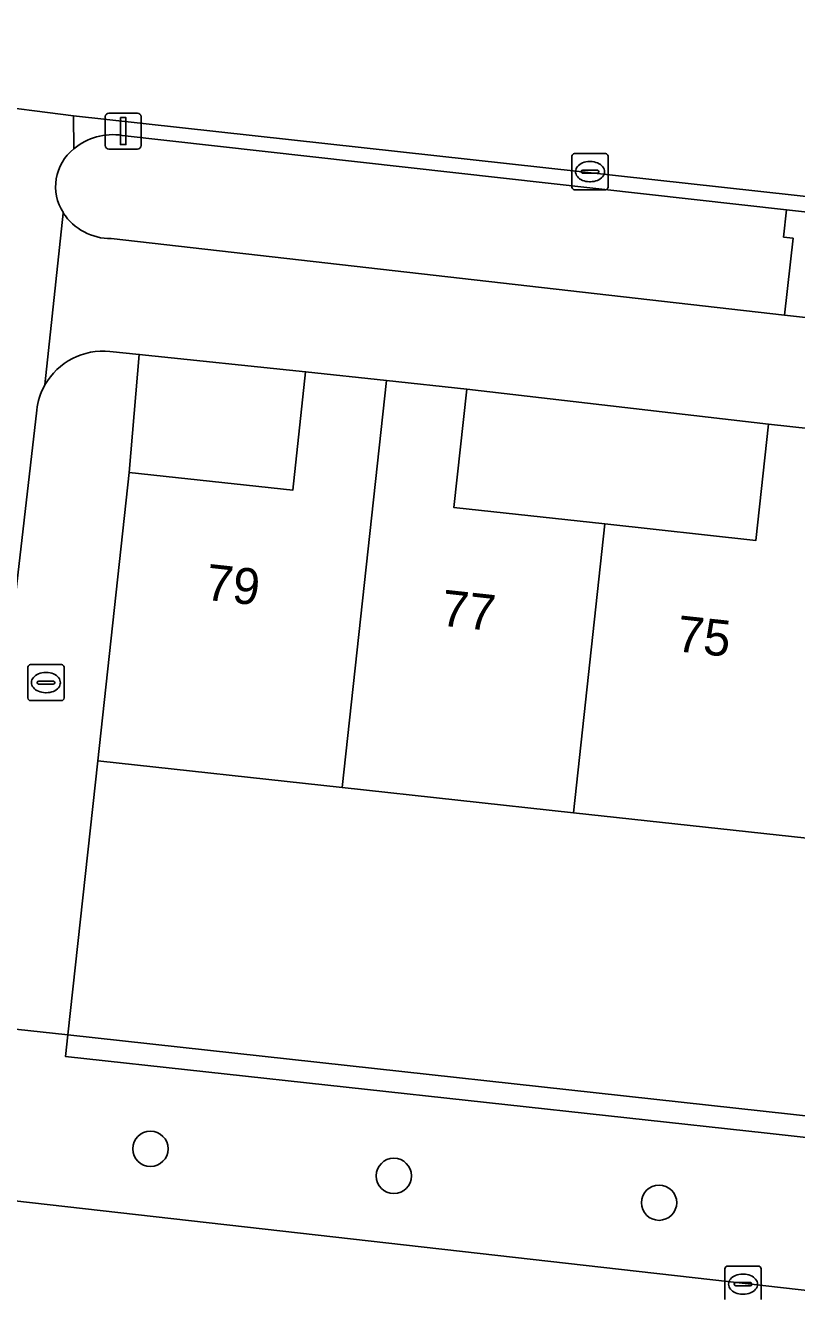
# Model space of a CAD drawing. Extents: x 161928 to 163071, y 386474 to 387428.
# Drawn here: x 162119.35 to 162140.71, y 387057.88 to 387093.2 of the extents above; entities that cross this region are included whole.
import ezdxf

# ---------------------------------------------------------------- set-up
doc = ezdxf.new("R2010")
doc.units = 0
for name, color, linetype in [('IMGEO_Boom', 7, 'Continuous'), ('IMGEO_Erf', 7, 'Continuous'), ('IMGEO_Groenvoorziening', 7, 'Continuous'), ('IMGEO_Haag', 7, 'Continuous'), ('IMGEO_Kolk', 7, 'Continuous'), ('IMGEO_Lichtmast', 7, 'Continuous'), ('IMGEO_Pand', 7, 'Continuous'), ('IMGEO_Pand_nummerreeks', 7, 'Continuous'), ('IMGEO_Rijbaan_lokaal_open', 7, 'Continuous'), ('IMGEO_Rioolput', 7, 'Continuous'), ('IMGEO_Voetpad_open', 7, 'Continuous')]:
    doc.layers.add(name, color=color, linetype=linetype)

msp = doc.modelspace()

# ---------------------------------------------------------------- linework, layer by layer
at = {"layer": 'IMGEO_Boom'}
for centre in [(162122.809, 387062.054), (162129.553, 387061.304), (162136.902, 387060.56)]:
    msp.add_circle(centre, 0.489, dxfattribs=at)
at = {"layer": 'IMGEO_Erf'}
for points in [[(162122.221, 387080.808), (162126.751, 387080.315), (162127.109, 387083.598), (162122.499, 387084.078)], [(162131.573, 387083.112), (162131.216, 387079.834), (162135.4, 387079.379), (162139.586, 387078.923), (162139.937, 387082.143)], [(162166.885, 387067.852), (162160.394, 387068.559), (162153.9, 387069.266), (162147.468, 387069.966), (162140.997, 387070.67), (162134.529, 387071.374), (162128.119, 387072.072), (162121.35, 387072.809), (162120.517, 387065.213), (162142.895, 387062.759), (162143.041, 387063.946), (162146.748, 387063.493), (162146.609, 387062.352), (162146.503, 387061.486), (162172.556, 387058.628), (162172.666, 387059.494), (162173.539, 387067.128)]]:
    msp.add_lwpolyline(points, close=True, dxfattribs=at)
at = {"layer": 'IMGEO_Groenvoorziening'}
for points in [[(162140.437, 387088.086), (162122.028, 387090.153)], [(162121.722, 387087.293), (162140.374, 387085.172), (162140.616, 387087.302), (162140.353, 387087.332), (162140.437, 387088.086)], [(162122.221, 387080.808), (162122.499, 387084.078), (162121.687, 387084.163)], [(162119.657, 387082.531), (162117.695, 387065.523), (162120.517, 387065.213), (162121.35, 387072.809), (162122.221, 387080.808)], [(162142.401, 387062.21), (162139.894, 387062.484), (162120.452, 387064.617), (162120.517, 387065.213), (162117.695, 387065.523), (162117.363, 387062.64)], [(162118.965, 387060.622), (162172.588, 387054.548)]]:
    msp.add_lwpolyline(points, dxfattribs=at)
msp.add_lwpolyline([(162120.517, 387065.213), (162120.452, 387064.617), (162139.894, 387062.484), (162142.401, 387062.21), (162142.366, 387061.437), (162146.437, 387060.889), (162172.491, 387058.032), (162172.556, 387058.628), (162146.503, 387061.486), (162146.491, 387061.389), (162142.783, 387061.843), (162142.822, 387062.163), (162142.895, 387062.759)], close=True, dxfattribs=at)
for centre, radius, start, end in [((162121.765, 387088.492), 1.681, 81.0144, 129.8573), ((162121.527, 387088.73), 1.346, 128.5231, 212.8129), ((162121.702, 387088.853), 1.561, 213.1519, 270.7524), ((162121.498, 387082.319), 1.853, 84.147, 150.4246), ((162121.495, 387082.321), 1.85, 150.4291, 173.4852)]:
    msp.add_arc(centre, radius, start, end, dxfattribs=at)
at = {"layer": 'IMGEO_Haag'}
for points in [[(162122.221, 387080.808), (162122.499, 387084.078), (162121.687, 387084.163)], [(162119.657, 387082.531), (162117.695, 387065.523), (162120.517, 387065.213), (162121.35, 387072.809), (162122.221, 387080.808)]]:
    msp.add_lwpolyline(points, dxfattribs=at)
msp.add_lwpolyline([(162120.517, 387065.213), (162120.452, 387064.617), (162139.894, 387062.484), (162142.401, 387062.21), (162142.366, 387061.437), (162146.437, 387060.889), (162172.491, 387058.032), (162172.556, 387058.628), (162146.503, 387061.486), (162146.491, 387061.389), (162142.783, 387061.843), (162142.822, 387062.163), (162142.895, 387062.759)], close=True, dxfattribs=at)
for centre, radius, start, end in [((162121.498, 387082.319), 1.853, 84.147, 150.4246), ((162121.495, 387082.321), 1.85, 150.4291, 173.4852)]:
    msp.add_arc(centre, radius, start, end, dxfattribs=at)
at = {"layer": 'IMGEO_Kolk'}
for p, q in [((162134.488, 387088.721), (162134.488, 387089.573)), ((162134.563, 387089.647), (162135.415, 387089.647)), ((162134.976, 387089.427), (162135.001, 387089.427)), ((162135.489, 387089.573), (162135.489, 387088.721)), ((162134.747, 387089.141), (162134.747, 387089.153)), ((162135.185, 387089.104), (162134.787, 387089.104)), ((162134.79, 387089.19), (162135.188, 387089.19)), ((162135.231, 387089.153), (162135.231, 387089.141)), ((162135.415, 387088.647), (162134.563, 387088.647)), ((162134.999, 387088.867), (162134.974, 387088.867)), ((162138.728, 387057.876), (162138.728, 387058.728)), ((162138.803, 387058.802), (162139.655, 387058.802)), ((162139.729, 387058.728), (162139.729, 387057.876)), ((162138.987, 387058.296), (162138.987, 387058.308)), ((162139.425, 387058.259), (162139.027, 387058.259)), ((162139.03, 387058.345), (162139.428, 387058.345)), ((162139.216, 387058.582), (162139.241, 387058.582)), ((162139.471, 387058.308), (162139.471, 387058.296)), ((162139.239, 387058.022), (162139.214, 387058.022))]:
    msp.add_line(p, q, dxfattribs=at)
for points in [[(162134.488, 387088.721), (162134.488, 387089.573)], [(162134.563, 387089.647), (162135.415, 387089.647)], [(162135.489, 387089.573), (162135.489, 387088.721)], [(162135.415, 387088.647), (162134.563, 387088.647)], [(162138.728, 387057.876), (162138.728, 387058.728)], [(162138.803, 387058.802), (162139.655, 387058.802)], [(162139.729, 387058.728), (162139.729, 387057.876)]]:
    msp.add_lwpolyline(points, dxfattribs=at)
for centre, radius, start, end in [((162134.565, 387089.571), 0.0765, 91.552, 178.448), ((162134.565, 387089.571), 0.0765, 91.552, 178.448), ((162135.413, 387089.571), 0.0765, 1.552, 88.448), ((162135.413, 387089.571), 0.0765, 1.552, 88.448), ((162134.787, 387089.15), 0.0403, 85.8775, 175.7526), ((162134.784, 387089.14), 0.0366, 178.938, 274.7102), ((162135.188, 387089.147), 0.043, 264.8664, 352.4533), ((162135.192, 387089.152), 0.0386, 1.7309, 96.639), ((162134.565, 387088.723), 0.0765, 181.552, 268.448), ((162134.565, 387088.723), 0.0765, 181.552, 268.448), ((162135.413, 387088.723), 0.0765, 271.552, 358.448), ((162135.413, 387088.723), 0.0765, 271.552, 358.448), ((162138.805, 387058.726), 0.0765, 91.552, 178.448), ((162138.805, 387058.726), 0.0765, 91.552, 178.448), ((162139.653, 387058.726), 0.0765, 1.552, 88.448), ((162139.653, 387058.726), 0.0765, 1.552, 88.448), ((162139.027, 387058.305), 0.0403, 85.8775, 175.7526), ((162139.024, 387058.295), 0.0366, 178.938, 274.7102), ((162139.428, 387058.302), 0.043, 264.8664, 352.4533), ((162139.432, 387058.307), 0.0386, 1.7309, 96.639)]:
    msp.add_arc(centre, radius, start, end, dxfattribs=at)
for centre, major_axis, ratio, start_param, end_param in [((162134.975, 387089.147), (-0.387, 0.002), 0.722429, 4.712389, 7.853982), ((162135, 387089.147), (-0.39, 0.002), 0.717154, 1.570796, 4.712389), ((162139.215, 387058.302), (-0.387, 0.002), 0.722429, 4.712389, 7.853982), ((162139.24, 387058.302), (-0.39, 0.002), 0.717154, 1.570796, 4.712389)]:
    msp.add_ellipse(centre, major_axis=major_axis, ratio=ratio, start_param=start_param, end_param=end_param, dxfattribs=at)
at = {"layer": 'IMGEO_Lichtmast'}
for p, q in [((162121.658, 387090.77), (162122.448, 387090.77)), ((162122.448, 387090.77), (162121.658, 387090.77)), ((162121.558, 387089.87), (162121.558, 387090.67)), ((162121.558, 387090.67), (162121.558, 387089.87)), ((162122.548, 387090.67), (162122.548, 387089.87)), ((162122.548, 387089.87), (162122.548, 387090.67)), ((162122.448, 387089.77), (162121.658, 387089.77)), ((162121.658, 387089.77), (162122.448, 387089.77))]:
    msp.add_line(p, q, dxfattribs=at)
msp.add_lwpolyline([(162121.978, 387090.645), (162122.128, 387090.645), (162122.128, 387089.895), (162121.978, 387089.895), (162121.978, 387090.645)], dxfattribs=at)
for centre, start, end in [((162121.658, 387090.67), 90, 180), ((162121.658, 387090.67), 90, 180), ((162122.448, 387090.67), 0, 90), ((162122.448, 387090.67), 360, 90), ((162121.658, 387089.87), 180, 270), ((162121.658, 387089.87), 180, 270), ((162122.448, 387089.87), 270, 0), ((162122.448, 387089.87), 270, 0)]:
    msp.add_arc(centre, 0.1, start, end, dxfattribs=at)
at = {"layer": 'IMGEO_Pand'}
for points in [[(162127.109, 387083.598), (162126.751, 387080.315), (162122.221, 387080.808), (162121.35, 387072.809), (162128.119, 387072.072), (162129.347, 387083.354)], [(162129.347, 387083.354), (162128.119, 387072.072), (162134.529, 387071.374), (162135.4, 387079.379), (162131.216, 387079.834), (162131.573, 387083.112)], [(162139.937, 387082.143), (162139.586, 387078.923), (162135.4, 387079.379), (162134.529, 387071.374), (162140.997, 387070.67), (162142.218, 387081.895)]]:
    msp.add_lwpolyline(points, close=True, dxfattribs=at)
at = {"layer": 'IMGEO_Rijbaan_lokaal_open'}
msp.add_lwpolyline([(162158.003, 387091.704), (162151.345, 387092.449), (162123.614, 387095.554), (162121.01, 387095.806), (162118.715, 387096.028), (162117.996, 387096.125), (162117.337, 387091.118), (162118.069, 387091.03), (162120.68, 387090.694), (162172.779, 387084.959), (162173.314, 387089.989), (162171.32, 387090.212), (162165.056, 387090.938)], close=True, dxfattribs=at)
at = {"layer": 'IMGEO_Rioolput'}
for p, q in [((162119.413, 387074.554), (162119.413, 387075.406)), ((162119.488, 387075.48), (162120.34, 387075.48)), ((162119.901, 387075.26), (162119.926, 387075.26)), ((162120.414, 387075.406), (162120.414, 387074.554)), ((162119.672, 387074.974), (162119.672, 387074.986)), ((162120.11, 387074.937), (162119.712, 387074.937)), ((162119.715, 387075.023), (162120.113, 387075.023)), ((162120.156, 387074.986), (162120.156, 387074.974)), ((162119.924, 387074.7), (162119.899, 387074.7)), ((162120.34, 387074.48), (162119.488, 387074.48))]:
    msp.add_line(p, q, dxfattribs=at)
for points in [[(162119.413, 387074.554), (162119.413, 387075.406)], [(162119.488, 387075.48), (162120.34, 387075.48)], [(162120.414, 387075.406), (162120.414, 387074.554)], [(162120.34, 387074.48), (162119.488, 387074.48)]]:
    msp.add_lwpolyline(points, dxfattribs=at)
for centre, radius, start, end in [((162119.49, 387075.404), 0.0765, 91.552, 178.448), ((162119.49, 387075.404), 0.0765, 91.552, 178.448), ((162120.338, 387075.404), 0.0765, 1.552, 88.448), ((162120.338, 387075.404), 0.0765, 1.552, 88.448), ((162119.712, 387074.983), 0.0403, 85.8775, 175.7526), ((162119.709, 387074.973), 0.0366, 178.938, 274.7102), ((162120.113, 387074.98), 0.043, 264.8664, 352.4533), ((162120.117, 387074.985), 0.0386, 1.7309, 96.639), ((162119.49, 387074.556), 0.0765, 181.552, 268.448), ((162119.49, 387074.556), 0.0765, 181.552, 268.448), ((162120.338, 387074.556), 0.0765, 271.552, 358.448), ((162120.338, 387074.556), 0.0765, 271.552, 358.448)]:
    msp.add_arc(centre, radius, start, end, dxfattribs=at)
for centre, major_axis, ratio, start_param, end_param in [((162119.9, 387074.98), (-0.387, 0.002), 0.722429, 4.712389, 7.853982), ((162119.925, 387074.98), (-0.39, 0.002), 0.717154, 1.570796, 4.712389)]:
    msp.add_ellipse(centre, major_axis=major_axis, ratio=ratio, start_param=start_param, end_param=end_param, dxfattribs=at)
at = {"layer": 'IMGEO_Voetpad_open'}
for points in [[(162120.688, 387089.783), (162120.68, 387090.694), (162118.069, 387091.03), (162117.337, 387091.118), (162116.088, 387091.27)], [(162172.779, 387084.959), (162120.68, 387090.694), (162120.688, 387089.783)], [(162122.028, 387090.153), (162140.437, 387088.086), (162141.924, 387087.919), (162146.233, 387087.435), (162146.891, 387087.286), (162147.482, 387086.962), (162148.107, 387086.096), (162148.062, 387085.58)], [(162119.886, 387083.234), (162120.395, 387088)], [(162120.395, 387088), (162119.886, 387083.234)], [(162151.315, 387084.04), (162146.491, 387084.512), (162145.806, 387084.555), (162141.292, 387085.068), (162140.374, 387085.172), (162121.722, 387087.293)], [(162121.687, 387084.163), (162122.499, 387084.078), (162127.109, 387083.598), (162129.347, 387083.354), (162131.573, 387083.112), (162139.937, 387082.143), (162142.218, 387081.895), (162144.499, 387081.647), (162152.882, 387080.737), (162155.122, 387080.493), (162157.366, 387080.249), (162165.859, 387079.279), (162168.102, 387079.035), (162170.347, 387078.79), (162174.733, 387078.159), (162177.465, 387077.766), (162177.594, 387078.928)], [(162117.363, 387062.64), (162117.695, 387065.523), (162119.657, 387082.531)], [(162172.588, 387054.548), (162118.965, 387060.622)]]:
    msp.add_lwpolyline(points, dxfattribs=at)
msp.add_lwpolyline([(162141.924, 387087.919), (162140.437, 387088.086), (162140.353, 387087.332), (162140.616, 387087.302), (162140.374, 387085.172), (162141.292, 387085.068), (162141.534, 387087.197), (162141.839, 387087.163)], close=True, dxfattribs=at)
for centre, radius, start, end in [((162121.765, 387088.492), 1.681, 81.0144, 129.8573), ((162121.527, 387088.73), 1.346, 128.5231, 212.8129), ((162121.702, 387088.853), 1.561, 213.1519, 270.7524), ((162121.498, 387082.319), 1.853, 84.147, 150.4246), ((162121.495, 387082.321), 1.85, 150.4291, 173.4852)]:
    msp.add_arc(centre, radius, start, end, dxfattribs=at)

# ---------------------------------------------------------------- texts
at = {"layer": 'IMGEO_Pand_nummerreeks'}
for s, p in [('79', (162124.305, 387077.28)), ('77', (162130.828, 387076.566)), ('75', (162137.352, 387075.853))]:
    msp.add_text(s, height=1, rotation=353.7547, dxfattribs=at).set_placement(p)

doc.saveas('drawing.dxf')
